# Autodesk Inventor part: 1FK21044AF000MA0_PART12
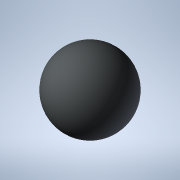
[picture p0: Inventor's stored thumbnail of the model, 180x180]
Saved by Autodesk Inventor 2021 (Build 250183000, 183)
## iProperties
Created: 2025-04
Part Number: 1FK21044AF000MA0_PART12
Material: Generic
Catalog Web Link: www.3dfindit.com
Description: -Servo synchronous motor
Document SubType Name: Modeling
Designer: psAdmin
Mass: 0.137258 g
Surface Area: 1.2868 cm^2
Volume: 0.137258 cm^3
Density: 1 g/cm^3
Appearance: PSOLRGB-212-217-219
Category: PARTsolutions
Title: 1FK21044AF000MA0_PART12
Author: Cadenas PARTsolutions
Comments: Servo synchronous motor
Sending System: PARTsolutions
Preprocessor: ST-DEVELOPER v19.3
PSOL_IDENT_0: {$CADENAS_DATA/23d-libs/siemens_ag/_cat_/39/c4/1fk21044af000ma0.prj},216 {VTYP=3D},{NB=1FK21044AF000
PSOL_IDENT_1: MA0_PART12},{LINA=1FK21044AF000MA0_PART12},{NN=1FK21044AF000MA0_PART12},{NOPRJ=TRUE},{DATE=19.08.202
PSOL_IDENT_2: 5 14:00:33},{GEOMDATE=30.07.2025 02:02:22},{VERSION=},{LINEID=10},{WBVAR=},{WBNUMERIC=}  {NB=1FK2104
PSOL_IDENT_3: 4AF000MA0_PART12},{LINA=1FK21044AF000MA0_PART12},{KT=DUMMY},{PREVIEW=../../../_pool_/cb/72/p_d211_xx
PSOL_IDENT_4: _00434j.png},{DESCSHORT=SIMOTICS S-1FK2 HD, SINAMICS S210 3AC 400V-480V, 1.27 Nm, 3000 rpm},{DESCLON
PSOL_IDENT_5: G=SIMOTICS S-1FK2 HD servo motor M0=1.27 Nm; PN = 0.4 kW at nN=3000 rpm (380-480 V); PN = 0.2 kW at
PSOL_IDENT_6: nN=1500 rpm (200-240 V); degree of protection IP64; cylindrical shaft D19x40mm; absolute encoder 22-
PSOL_IDENT_7: bit + 12-bit multiturn (encoder AM22DQC); with OCC interface; plug size M17, rotatable; SIMOTICS S-1
PSOL_IDENT_8: FK2 servomotorfor a wide range of uses in industrial environments. SIMOTICS S‑1FK2 servomotors are c
PSOL_IDENT_9: ompact synchronous motors with a high dynamic performance that set themselves apart as a result of t
PSOL_IDENT_10: heir high power density, degree of protection and overload capability. The motors are available in t
PSOL_IDENT_11: wo variants: as High Dynamic variant (highest dynamic performance as a result of the low intrinsic m
PSOL_IDENT_12: oment of inertia for applications demanding a high dynamic performance with low moved masses) - and
PSOL_IDENT_13: as Compact variant (precise and stable closed-loop control for medium up to large moved masses as a
PSOL_IDENT_14: result of a medium intrinsic moment of inertia). SIMOTICSS‑1FK2 servomotors fully exploit their stre
PSOL_IDENT_15: ngths in a system with the SINAMICSS210 frequency converter and simple connection using the one cabl
PSOL_IDENT_16: e connection (OCC). Advantages include the short control and positioning times, fast and precise cor
PSOL_IDENT_17: rection of disturbing quantities as well as stable control with a high dynamic performance. The serv
PSOL_IDENT_18: o motors can be configured to address a wide range of requirements. For example with and without hol
PSOL_IDENT_19: ding brake, IP64 or IP65 degree of protection, singleturn or multiturn absolute encoders - to name j
PSOL_IDENT_20: ust a few. Further, the servomotors are available in different shaft heights extending from 20 to 10
PSOL_IDENT_21: 0. A shaft sealing ring is available to achieve an IP65 degree of protection and for subsequent moun
PSOL_IDENT_22: ting at the motor or as spare part. SIMOTICS - the optimum motor for each and every motion control a
PSOL_IDENT_23: pplication.},{INTNO=804766906428},{SUPPLIERALTNO=1FK2104-4AF00-0MA0},{MANUID=1FK21044AF000MA0},{MANU
PSOL_IDENT_24: NAME=Siemens},{MANUTYPEDESC=Synchronous motor 1FK2-HD 1.27 NM},{AAU732=SIMOTICS},{AAO057=S-1FK2},{AA
PSOL_IDENT_25: U734=SIMOTICS S-1FK2 HD servo motor M0=1.27 Nm; PN = 0.4 kW at nN=3000 rpm (380-480 V); PN = 0.2 kW
PSOL_IDENT_26: at nN=1500 rpm (200-240 V); degree of protection IP64; cylindrical shaft D19x40mm; absolute encoder
PSOL_IDENT_27: 22-bit + 12-bit multiturn (encoder AM22DQC); with OCC interface; plug size M17, rotatable;},{AAW338=
PSOL_IDENT_28: Synchronous motor 1FK2-HD 1.27 NM},{AAO742=SIMOTICS},{AAO663=4042948693322},{NOCUPEROU=1},{PRICEQUAN
PSOL_IDENT_29: TITY=1},{QUANTITYMIN=1},{QUANTITYINT=1},{CTN=85015100},{COO=DE},{AAO676=1FK2104-4AF00-0MA0},{AAO677=
PSOL_IDENT_30: Siemens AG},{ORDERUNIT=C62},{CONTENTUNIT=C62}
NB: 1FK21044AF000MA0_PART12
NT: Servo synchronous motor
NBSYN: $MANUID._PART12
LINA: 1FK21044AF000MA0_PART12
CATALOG: SIEMENS
PREVIEW: ../../../_pool_/cb/72/p_d211_xx_00434j.png
DESCSHORT: SIMOTICS S-1FK2 HD, SINAMICS S210 3AC 400V-480V, 1.27 Nm, 3000 rpm
DESCLONG: SIMOTICS S-1FK2 HD servo motor M0=1.27 Nm; PN = 0.4 kW at nN=3000 rpm (380-480 V); PN = 0.2 kW at nN=1500 rpm (200-240 V); degree of protection IP64; cylindrica
INTNO: 804766906428
SUPPLIERALTNO: 1FK2104-4AF00-0MA0
MANUID: 1FK21044AF000MA0
MANUNAME: Siemens
MANUTYPEDESC: Synchronous motor 1FK2-HD 1.27 NM
AAU732: SIMOTICS
AAO057: S-1FK2
AAU734: SIMOTICS S-1FK2 HD servo motor M0=1.27 Nm; PN = 0.4 kW at nN=3000 rpm (380-480 V); PN = 0.2 kW at nN=1500 rpm (200-240 V); degree of protection IP64; cylindrica
AAW338: Synchronous motor 1FK2-HD 1.27 NM
AAO742: SIMOTICS
AAO663: 4042948693322.0
NOCUPEROU: 1
PRICEQUANTITY: 1
QUANTITYMIN: 1
QUANTITYINT: 1
CTN: 85015100
COO: DE
ARTICLENO: 1FK21044AF000MA0_PART12
BOMINFO: 1FK21044AF000MA0_PART12
CREATOR: CADENAS GmbH
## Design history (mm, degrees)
feature "2025_04_17_15_01_28_0038"
body "Solid1"
